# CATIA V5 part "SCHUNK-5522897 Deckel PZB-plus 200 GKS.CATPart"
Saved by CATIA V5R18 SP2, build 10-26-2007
Part number: SCHUNK-5522897 Deckel PZB-plus 200 GKS
Property "ParasolidId": 27
Property "PSOL_INSTNR": 4
Bounding box of the stored display mesh (mm): x -100 to 100, y 0 to 43, z -100 to 100
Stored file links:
  C:\Users\MIRCEA\Desktop\PRRO\CATIAV5\SCHUNK-5522897 Deckel PZB-plus 200 GKS.CATPart
  C:\Program Files (x86)\Dassault Systemes\B21\intel_a\startup\materials\French\Catalog.CATMaterial
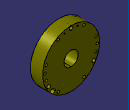
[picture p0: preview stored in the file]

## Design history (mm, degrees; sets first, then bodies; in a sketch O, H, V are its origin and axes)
Body1 "SCHUNK-5522897 Deckel PZB-plus 200 GKS(1)" (main body)
  Solid1: solid without history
